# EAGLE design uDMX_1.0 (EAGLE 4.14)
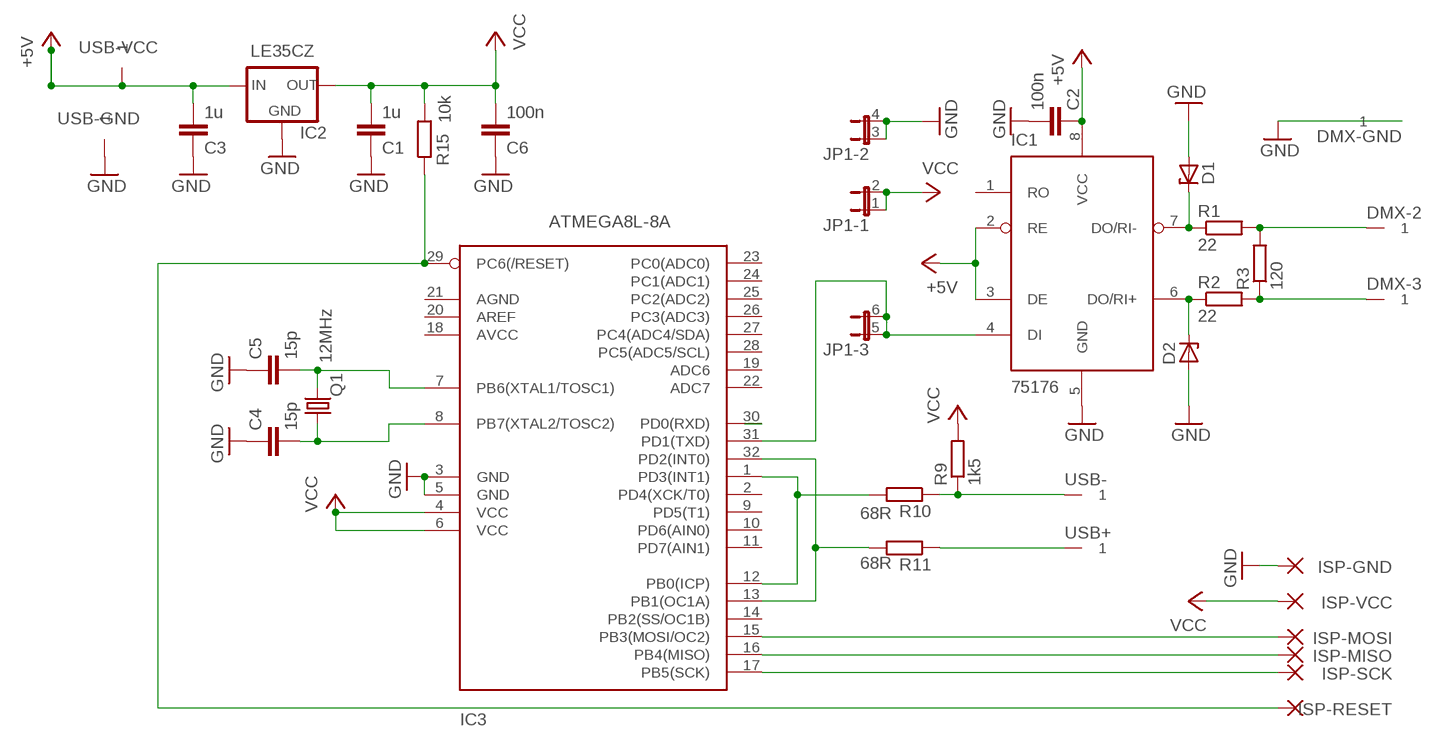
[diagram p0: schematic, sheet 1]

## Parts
C1  1u  C-EUC0603  [C0603]
C2  100n  C-EUC0603  [C0603]
C3  1u  C-EUC0603  [C0603]
C4  15p  C-EUC0805  [C0805]
C5  15p  C-EUC0805  [C0805]
C6  100n  C-EUC0603  [C0603]
D1  ZENER-DIODESOD80C  [SOD80C]
D2  ZENER-DIODESOD80C  [SOD80C]
DMX-2  ELLIPTICAL-PAD  [ELLIPTICAL]
DMX-3  ELLIPTICAL-PAD  [ELLIPTICAL]
DMX-GND  ELLIPTICAL-PAD  [ELLIPTICAL]
IC1  75176  [SO08]
IC2  LE35CZ  78LXX  [78LXX]
IC3  ATMEGA8L-8A  [TQFP32-08]
ISP-GND  SMD2  [SMD2]
ISP-MISO  SMD2  [SMD2]
ISP-MOSI  SMD2  [SMD2]
ISP-RESET  SMD2  [SMD2]
ISP-SCK  SMD2  [SMD2]
ISP-VCC  SMD2  [SMD2]
JP1  JP3QE  [JP3Q]
Q1  12MHz  CRYTALHC49U-V  [HC49U-V]
R1  22  R-EU_M0805  [M0805]
R2  22  R-EU_M0805  [M0805]
R3  120  R-EU_M0805  [M0805]
R9  1k5  R-EU_M0805  [M0805]
R10  68R  R-EU_M0805  [M0805]
R11  68R  R-EU_M0805  [M0805]
R15  10k  R-EU_0309/10  [0309/10]
USB+  ELLIPTICAL-PAD  [ELLIPTICAL]
USB-  ELLIPTICAL-PAD  [ELLIPTICAL]
USB-GND  ELLIPTICAL-PAD  [ELLIPTICAL]
USB-VCC  ELLIPTICAL-PAD  [ELLIPTICAL]

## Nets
+5V: C2.1 C3.2 IC1.2(RE) IC1.3(DE) IC1.8(VCC) IC2.IN USB-VCC.A1
D-: R9.1 R10.1 USB-.A1
DMX2: DMX-2.A1 R1.2 R3.2
DMX3: DMX-3.A1 R2.2 R3.1
GND: C1.1 C2.2 C3.1 C4.1 C5.1 C6.1 D1.A D2.A DMX-GND.A1 IC1.5(GND) IC2.GND IC3.3(GND) IC3.5(GND) ISP-GND.1(P) JP1.3 JP1.4 USB-GND.A1
N$1: IC3.1(PD3(INT1)) IC3.12(PB0(ICP)) R10.2
N$2: IC3.30(PD0(RXD))
N$3: D1.C IC1.7(DO/RI-) R1.1
N$4: D2.C IC1.6(DO/RI+) R2.1
N$5: IC1.4(DI) IC3.31(PD1(TXD)) JP1.5 JP1.6
N$6: IC3.13(PB1(OC1A)) IC3.32(PD2(INT0)) R11.2
N$10: R11.1 USB+.A1
N$37: C4.2 IC3.8(PB7(XTAL2/TOSC2)) Q1.1
N$38: C5.2 IC3.7(PB6(XTAL1/TOSC1)) Q1.2
SPI_MISO: IC3.16(PB4(MISO)) ISP-MISO.1(P)
SPI_MOSI: IC3.15(PB3(MOSI/OC2)) ISP-MOSI.1(P)
SPI_RESET: IC3.29(PC6(/RESET)) ISP-RESET.1(P) R15.1
SPI_SCK: IC3.17(PB5(SCK)) ISP-SCK.1(P)
VCC: C1.2 C6.2 IC2.OUT IC3.4(VCC) IC3.6(VCC) ISP-VCC.1(P) JP1.1 JP1.2 R9.2 R15.2
Unconnected: IC1.1(RO) IC3.2(PD4(XCK/T0)) IC3.9(PD5(T1)) IC3.10(PD6(AIN0)) IC3.11(PD7(AIN1)) IC3.14(PB2(SS/OC1B)) IC3.18(AVCC) IC3.19(ADC6) IC3.20(AREF) IC3.21(AGND) IC3.22(ADC7) IC3.23(PC0(ADC0)) IC3.24(PC1(ADC1)) IC3.25(PC2(ADC2)) IC3.26(PC3(ADC3)) IC3.27(PC4(ADC4/SDA)) IC3.28(PC5(ADC5/SCL))

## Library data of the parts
C1-C6 = rcl:C-EU: CAPACITOR, European symbol
D1 D2 = diode:ZENER-DIODE: Z-Diode
DMX-2 DMX-3 DMX-GND USB+ USB- USB-GND USB-VCC = special-pad:ELLIPTICAL-PAD
IC1 = mexxlib:75176
IC2 = v-reg:78LXX: VOLTAGE REGULATOR
IC3 = avr:ATMEGA8: MICROCONTROLLER 8 Kbytes FLASH 1 kbytes SRAM 512 bytes EEPROM USART 6-channel 10 bit ADC 2-channel 8 bit ADC
ISP-GND ISP-MISO ISP-MOSI ISP-RESET ISP-SCK ISP-VCC = wirepad:SMD2: SMD PAD
JP1 = jumper:JP3QE: JUMPER
Q1 = crystal:CRYTAL: CRYSTAL
R1-R3 R9-R11 R15 = rcl:R-EU_: RESISTOR, European symbol

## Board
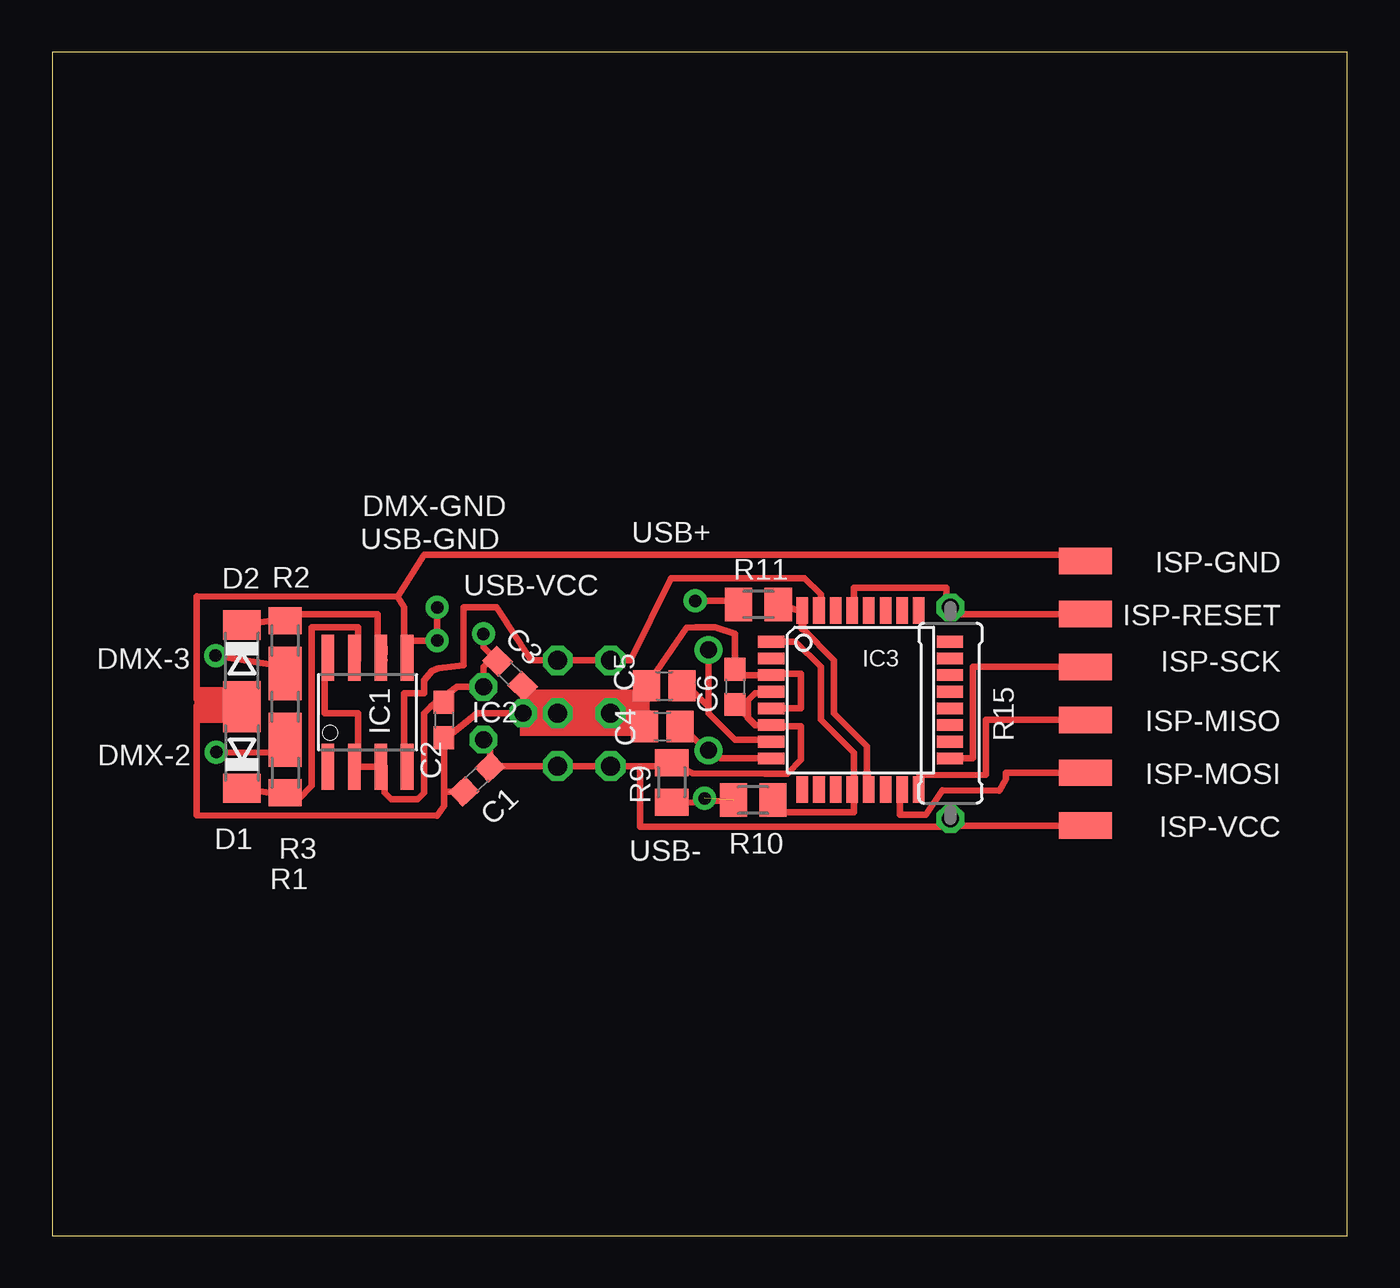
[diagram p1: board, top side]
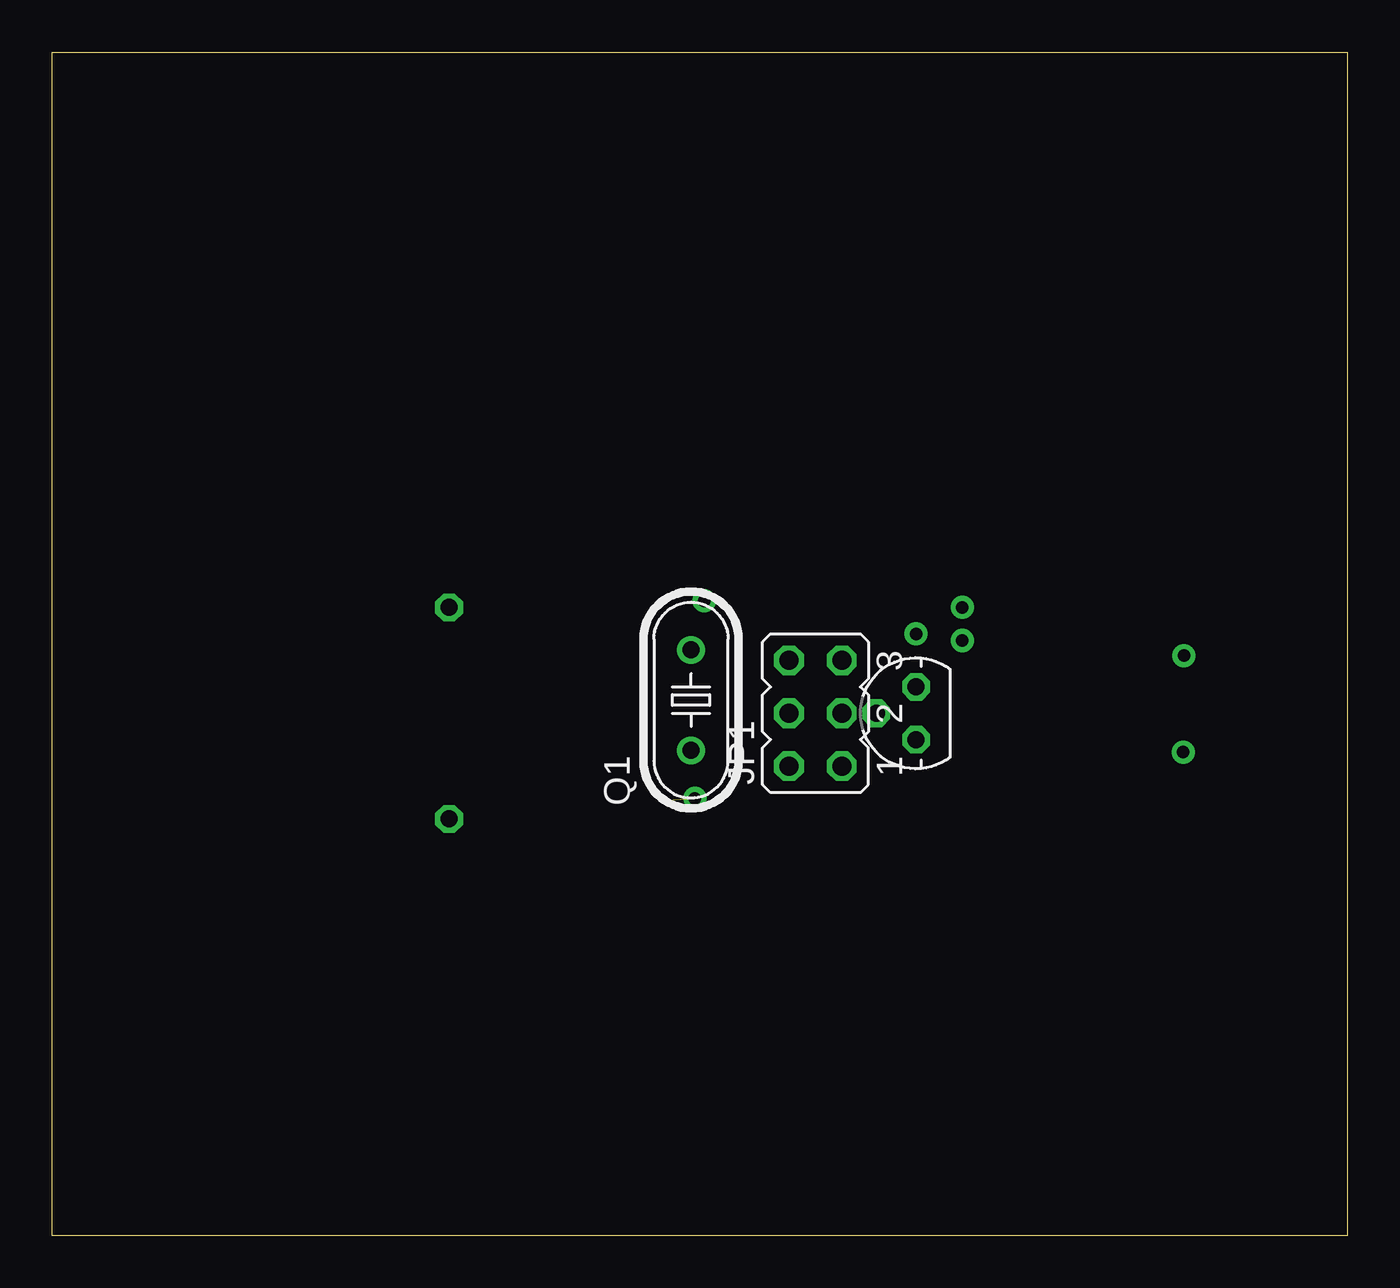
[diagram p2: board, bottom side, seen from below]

Size 62.22 x 56.82 mm. Coordinates in mm from the lower left corner, seen from the top.
Outline: 0,0 62.22,0 62.22,56.82 0,56.82 0,0
Copper layers (1*16): Top 0.035mm / dielectric 1.5mm / Bottom 0.035mm
Design rules "default": minimum track width 10mil, minimum drill 24mil, track to track 8mil, track to pad 8mil, pad to pad 8mil, via to via 8mil, smd to smd 8mil, copper to edge 40mil, drill to drill 8mil, minimum pad ring 10mil, minimum via ring 8mil, stop-mask expansion 4mil, vias tented up to drill 0mil, thermal gap 10mil

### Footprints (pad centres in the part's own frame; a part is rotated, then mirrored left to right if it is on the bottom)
C0603 = smd 1.1 x 1: 1 -0.85,0; 2 0.85,0
C0805 = smd 1.3 x 1.5: 1 -0.85,0; 2 0.85,0
SOD80C = smd 1.4 x 1.8: A 1.7,0; C -1.7,0
ELLIPTICAL = drill 0.6 round: A1 0,0
SO08 = smd 0.61 x 2.21: 1 -1.905,-2.616; 2 -0.635,-2.616; 3 0.635,-2.616; 4 1.905,-2.616; 5 1.905,2.616; 6 0.635,2.616; 7 -0.635,2.616; 8 -1.905,2.616
78LXX = drill 0.813 octagon: GND 0,1.905; IN 1.27,0; OUT -1.27,0
TQFP32-08 = smd 1.27 x 0.559: 1 -4.293,2.8; 2 -4.293,2; 3 -4.293,1.2; 4 -4.293,0.4; 5 -4.293,-0.4; 6 -4.293,-1.2; 7 -4.293,-2; 8 -4.293,-2.8; 17 4.293,-2.8; 18 4.293,-2; 19 4.293,-1.2; 20 4.293,-0.4; 21 4.293,0.4; 22 4.293,1.2; 23 4.293,2; 24 4.293,2.8 | smd 0.559 x 1.27: 9 -2.8,-4.293; 10 -2,-4.293; 11 -1.2,-4.293; 12 -0.4,-4.293; 13 0.4,-4.293; 14 1.2,-4.293; 15 2,-4.293; 16 2.8,-4.293; 25 2.8,4.293; 26 2,4.293; 27 1.2,4.293; 28 0.4,4.293; 29 -0.4,4.293; 30 -1.2,4.293; 31 -2,4.293; 32 -2.8,4.293
SMD2 = smd 1.27 x 2.54: 1 0,0
JP3Q = drill 0.914 octagon: 1 -2.54,-1.27; 2 -2.54,1.27; 3 0,-1.27; 4 0,1.27; 5 2.54,-1.27; 6 2.54,1.27
HC49U-V = drill 0.813 round: 1 -2.413,0; 2 2.413,0
M0805 = smd 1.3 x 1.6: 1 -0.95,0; 2 0.95,0
0309/10 = drill 0.813 octagon: 1 -5.08,0; 2 5.08,0

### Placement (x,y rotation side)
C1  20.41,21.9 43.2 top
C2  18.82,24.76 270 top
C3  21.99,26.98 135.4 top
C4  29.31,24.44 0 top
C5  29.41,26.4 0 top
C6  32.8,26.35 270 top
D1  9.12,23.17 90 top
D2  9.12,27.62 270 top
DMX-2  7.89,23.21 0 top
DMX-3  7.86,27.84 0 top
DMX-GND  18.5,30.16 0 top
IC1  15.15,25.13 0 top
IC2  20.72,25.08 90 bottom
IC3  38.83,25.71 0 top
ISP-GND  49.63,32.38 90 top
ISP-MISO  49.63,24.76 90 top
ISP-MOSI  49.63,22.22 90 top
ISP-RESET  49.63,29.84 90 top
ISP-SCK  49.63,27.3 90 top
ISP-VCC  49.63,19.68 90 top
JP1  25.55,25.08 90 bottom
Q1  31.53,25.71 90 bottom
R1  11.2,22.22 90 top
R2  11.2,28.57 270 top
R3  11.2,25.39 270 top
R9  29.76,21.76 90 top
R10  33.67,20.91 0 top
R11  33.93,30.3 0 top
R15  43.15,25.08 270 top
USB+  30.89,30.48 0 top
USB-  31.34,20.99 0 top
USB-GND  18.5,28.57 0 top
USB-VCC  20.72,28.89 0 top

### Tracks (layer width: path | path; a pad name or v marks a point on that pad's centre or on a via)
+5V
  Top 0.305: IC1.8 13.1,27.74 13.1,25.08 14.69,25.08 14.69,22.51 | IC1.2 14.69,22.51 | 14.69,22.51 IC1.3 15.93,22.51 15.96,22.54 15.96,21.27 16.28,20.95 17.55,20.95 17.87,21.27 17.87,25.08 18.18,25.39 | 18.18,25.39 C2.1 | 18.18,25.39 19.45,26.35 IC2.IN 20.72,27.3 21.25,27.82 | 21.25,27.82 21.36,27.93 | 21.25,27.82 C3.2 21.25,27.73 20.72,28.25 USB-VCC.A1
D-  (1 unrouted)
  Top 0.305: 29.94,20.81 29.94,20.95 | 29.94,20.81 R9.1 29.62,20.81 29.62,21.27 | R10.1 29.94,20.76 29.94,20.81
DMX2
  Top 0.305: R1.2 R3.2 | R1.2 | DMX-2.A1 R1.2
DMX3
  Top 0.305: 11.2,27.3 R3.1 | 11.2,27.3 R2.2 | DMX-3.A1 11.2,27.3
GND
  Top 0.305: IC3.5 35.97,25.31 35.97,26.98 34.39,26.98 34.39,26.91 IC3.3 32.48,26.91 C6.1 | C6.1 32.48,27.3 | 16.6,30.67 6.94,30.7 6.94,25.75 7.69,25.95 D2.A D1.A 9.12,24.44 8.8,24.76 7.26,24.8 6.94,25.43 6.94,20.18 18.5,20.15 18.82,20.63 18.82,21.27 | 16.6,30.67 16.91,30.16 16.91,28.57 | IC1.5 17.04,27.74 16.91,27.62 16.91,28.57 | 18.82,23.81 20.41,25.08 IC2.GND 22.74,25.19 | 18.82,21.27 18.82,23.81 | 18.82,23.81 C2.2 | DMX-GND.A1 USB-GND.A1 16.91,28.57 | 28.46,24.23 28.35,24.13 | 28.46,24.23 C4.1 28.67,24.44 28.67,25.08 JP1.4 JP1.3 24.17,25.19 22.74,25.19 | 28.46,24.23 28.56,24.33 C5.1 30.48,29.19 30.89,29.21 31.83,29.21 32.8,28.89 C6.1 | C1.1 18.87,21.32 18.82,21.27 | 22.74,25.19 C3.1 | ISP-GND.1 49.31,32.7 17.87,32.7 16.6,30.67
N$1
  Top 0.305: 38.51,21.27 38.51,21.42 IC3.12 38.43,21.35 | IC3.1 35.71,28.51 36.93,27.3 36.93,24.76 38.51,23.17 38.51,21.27 | 38.43,21.35 38.51,21.27 | 38.43,21.35 38.51,21.35 38.51,20.32 34.93,20.32 34.53,20.65 R10.2
N$3
  Top 0.305: D1.C 10.99,21.16 11.2,20.95 R1.1 11.84,20.95 12.47,21.59 12.47,29.21 14.69,29.21 14.69,27.62 14.57,27.74 IC1.7
N$4
  Top 0.305: 15.96,27.62 15.79,27.62 IC1.6 | 15.79,27.93 15.96,28.25 15.96,27.93 15.79,27.93 | IC1.6 15.79,27.93 | 15.79,27.93 15.64,27.93 | 11.4,29.64 11.2,29.84 R2.1 11.51,29.52 11.83,29.84 15.65,29.84 15.64,29.21 15.64,27.62 15.77,27.74 IC1.6 | D2.C 11.4,29.64 | 11.4,29.64 11.52,29.52
N$5
  Top 0.305: 27.14,27.62 27.77,27.62 29.74,31.56 36.15,31.56 36.93,30.79 36.93,30.16 36.83,30.06 IC3.31 | IC1.4 16.94,22.51 16.91,22.54 16.91,26.03 17.87,26.03 17.87,26.67 18.24,27.12 18.56,27.23 19.77,27.38 19.77,30.16 21.36,30.16 23.01,27.62 JP1.5 27.14,27.62 | 27.14,27.62 JP1.6
N$6
  Top 0.305: 36.03,29.15 37.56,27.62 37.56,25.08 39.15,23.49 39.15,22.22 | 35.97,30 35.97,30.16 | IC3.32 35.97,30 | R11.2 35.97,29.98 35.97,30
  Top 0.406: IC3.32 36.03,29.9 35.97,29.84 35.97,29.52 36.03,29.58 IC3.32 | 36.03,29.15 IC3.32 | IC3.13 39.23,21.82 39.15,21.9 39.15,22.22
N$10
  Top 0.305: 32.8,30.3 32.8,30.16 | 32.8,30.3 R11.1 | USB+.A1 32.8,30.48 32.8,30.3
N$37
  Top 0.305: IC3.8 32.11,22.91 31.53,23.49 Q1.1 31.4,23.3 30.26,24.44 C4.2
N$38
  Top 0.305: 31.53,25.39 31.53,25.08 32.8,23.81 34.39,23.81 34.48,23.71 IC3.7 | 31.53,25.39 Q1.2 | C5.2 30.53,26.4 31.53,25.39
SPI_MISO
  Top 0.305: IC3.16 41.63,21.32 41.67,22.11 44.85,22.12 44.85,24.76 44.86,24.76 | 44.86,24.76 | 44.86,24.76 ISP-MISO.1
SPI_MOSI
  Top 0.305: IC3.15 40.74,21.42 40.72,20.21 41.97,20.21 42.76,21.37 45.51,21.35 45.82,21.9 45.82,22.22 ISP-MOSI.1
SPI_RESET
  Top 0.305: IC3.29 38.51,30 38.51,31.11 42.96,31.11 42.96,30.16 | 42.96,30.16 | 42.96,30.16 R15.1 42.96,30.16 | ISP-RESET.1 43.59,29.84 42.96,30.16
SPI_SCK
  Top 0.305: IC3.17 43.28,22.91 | 43.28,22.91 43.59,22.91 | 43.28,22.91 44.23,22.91 44.23,27.3 ISP-SCK.1
VCC
  Top 0.305: 33.75,24.51 IC3.6 34.46,24.51 34.39,24.44 35.97,24.44 35.97,22.86 35.31,22.17 34.25,22.17 30.76,22.21 R9.2 29.45,22.72 29.31,22.54 27.77,22.54 | 33.75,24.51 33.43,24.83 33.43,25.71 33.75,26.03 34.7,26.03 34.7,26.11 IC3.4 | 33.75,24.51 34.07,24.44 | C6.2 33.75,24.54 33.75,24.51 | IC2.OUT 21.04,23.81 21.04,22.54 | 21.04,22.54 21.04,22.22 21.03,22.24 C1.2 21.03,22.52 21.04,22.54 | 21.04,22.54 JP1.1 27.14,22.54 | 27.14,22.54 27.77,22.54 | 27.14,22.54 JP1.2 | 27.77,22.54 28.24,22.52 28.23,19.62 42.96,19.62 42.96,20 R15.2 42.96,20.19 42.64,19.68 ISP-VCC.1
(copper drawn outside any net)
  shapes: Top area x2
